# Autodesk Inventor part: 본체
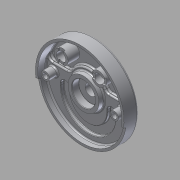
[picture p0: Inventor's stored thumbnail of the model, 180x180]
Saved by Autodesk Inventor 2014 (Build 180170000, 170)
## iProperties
Created: 2015-06
Part Number: 본체
Material: 알루미늄 6061
Document SubType Name: Modeling
Designer: MYHOME
Density: 2.71 g/cm^3
Appearance: 알루미늄 - 평지
Mass: 1069.97 g
Surface Area: 1036.84 cm^2
Volume: 394.821 cm^3
Author: MYHOME
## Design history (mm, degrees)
sketch "스케치1"
  geometry: C1 r 95 at (0, 0); 1 further point
  constraints: 1 centre point, 1 coincident
  dimensions: "d0" = 190 diameter of C1
extrude "돌출1" new body sketch "스케치1" distance "d1" = 32; taper "d2" = 0 deg
sketch "스케치2"
  geometry: C1 r 95 at (0, 0) reference; C2 r 90 at (0, 0)
  constraints: 1 centre point, 1 coincident
  dimensions: "d3" = 180 diameter of C2
extrude "돌출2" cut sketch "스케치2" distance "d4" = 25; taper "d5" = 0 deg
sketch "스케치4"
  geometry: L1 (0, 0)-(-95, 0); L2 (0, 0)-(-94.075, -13.221); L3 (0, 0)-(95, 0); L4 (0, 0)-(94.075, -13.221); A1 r 95 centre (0, 0) between (-95, 0) and (-94.075, -13.221) reference
  constraints: 8 end point, 4 point on circle, 1 collinear, 1 horizontal
  dimensions: "d6" = 8 deg angle of L1 L2; "d7" = 8 deg angle of L4 L3
extrude "돌출3" cut sketch "스케치4" distance "d8" = 5; taper "d9" = 0 deg
sketch "스케치6"
  geometry: L1 (-88.566, 16)-(-38.833, 16); L2 (38.833, 16)-(88.566, 16); A1 r 90 centre (0, 0) between (-88.566, 16) and (88.566, 16) reference; A2 r 42 centre (0, 0) between (38.833, 16) and (-38.833, 16)
  constraints: 4 end point, 4 point on circle, 2 horizontal, 1 centre point, 1 coincident, 1 collinear
  dimensions: "d15" = 42 radius of A2; "d17" = 16 distance from line of A1.centre L2
extrude "돌출4" join sketch "스케치6" distance "d18" = 7; taper "d19" = 0 deg
fillet "모깎기1" dims "d20" = 10
sketch "스케치7"
  geometry: C1 r 15 at (-40, 52); A1 r 90 centre (0, 0) between (85.114, 29.25) and (-85.114, 29.25) reference
  constraints: 1 centre point
  dimensions: "d21" = 30 diameter of C1; "d22" = 40 horizontal distance of A1.centre C1.centre; "d23" = 52 vertical distance of A1.centre C1.centre
extrude "돌출5" join sketch "스케치7" distance "d24" = 25; taper "d25" = 0 deg
sketch "스케치8"
  geometry: C1 r 15 at (0, 0) reference; C2 r 10 at (0, 0); 1 further point
  constraints: 1 centre point, 1 coincident
  dimensions: "d26" = 20 diameter of C2
extrude "돌출6" cut sketch "스케치8" stored distance "d27" = 25; taper "d28" = 0 deg
sketch "스케치9"
  geometry: L1 (-6, 15)-(6, 15); L2 (6, 15)-(6, -15); L3 (6, -15)-(-6, -15); L4 (-6, -15)-(-6, 15); C1 r 10 at (0, 0) reference; C2 r 15 at (0, 0) reference; 2 further points
  constraints: 8 end point, 2 parallel, 2 tangent, 1 horizontal, 1 midpoint, 1 perpendicular, 1 vertical alignment
  dimensions: "d29" = 12 distance of L2.end L3.end
extrude "돌출7" cut sketch "스케치9" distance "d31" = 3; taper "d32" = 0 deg
sketch "스케치10"
  geometry: L1 (-45.033, 16)-(-75.657, 16) reference; L2 (-50, -14)-(-50, -24); L3 (-41, -14)-(-41, -19); L4 (-59, -19)-(-59, -14); L5 (50, -14)-(50, -24); L6 (41, -14)-(41, -19); L7 (59, -19)-(59, -14); A1 r 90 centre (0, 0) between (-85.114, 29.25) and (85.114, 29.25) reference; A2 r 50 centre (0, -19) between (-50, -19) and (50, -19); A3 r 59 centre (0, -19) between (-59, -19) and (59, -19); A4 r 41 centre (0, -19) between (-41, -19) and (41, -19); A5 r 9 centre (-50, -19) between (-41, -19) and (-59, -19); A6 r 9 centre (50, -19) between (59, -19) and (41, -19); A7 r 9 centre (-50, -14) between (-41, -14) and (-59, -14); A8 r 9 centre (50, -14) between (59, -14) and (41, -14); 2 further points
  constraints: 16 end point, 14 point on circle, 8 tangent, 7 centre point, 3 parallel, 2 coincident, 2 horizontal alignment, 2 midpoint, 1 perpendicular, 1 vertical alignment
  dimensions: "d34" = 18 diameter of A6; "d35" = 59 radius of A3; "d36" = 19 distance of A2.centre A1.centre; "d38" = 5 distance of L2.start point (-50, -19); "d41" = 5 distance of L5.start point (50, -19)
extrude "돌출8" cut sketch "스케치10" distance "d42" = 7; taper "d43" = 0 deg
chamfer "모따기1" distance "d44" = 1; stored, may be unused: second distance "d45" = 2, angle "d46" = 45 deg
fillet "모깎기2" dims "d47" = 1
sketch "스케치11"
  geometry: C1 r 35 at (0, 0); A1 r 42 centre (0, 0) between (36.373, 21) and (-36.373, 21) reference
  constraints: 1 centre point, 1 coincident
  dimensions: "d48" = 70 diameter of C1
extrude "돌출9" join sketch "스케치11" distance "d49" = 10; taper "d50" = -10 deg
sketch "스케치12"
  geometry: C1 r 9 at (-74, 0); A1 r 90 centre (0, 0) between (-85.114, 29.25) and (85.114, 29.25) reference
  constraints: 1 centre point, 1 horizontal alignment
  dimensions: "d65" = 18 diameter of C1; "d66" = 74 distance of A1.centre C1.centre
extrude "돌출10" join sketch "스케치12" stored distance "d67" = 10; taper "d68" = 0 deg
fillet "모깎기5" dims "d69" = 3
sketch "스케치13"
  geometry: L1 (-15, 6)-(15, 6); L2 (15, 6)-(15, -6); L3 (15, -6)-(-15, -6); L4 (-15, -6)-(-15, 6); C1 r 10 at (0, 0) reference; C2 r 15 at (0, 0) reference; 2 further points
  constraints: 8 end point, 2 parallel, 2 tangent, 1 horizontal, 1 horizontal alignment, 1 midpoint, 1 perpendicular
  dimensions: "d70" = 12 distance of L1.end L2.end
extrude "돌출11" cut sketch "스케치13" distance "d71" = 3; taper "d72" = 0 deg
sketch "스케치16"
  geometry: C1 r 9 at (74, 0) reference; C2 r 9 at (-74, 0) reference; 2 further points
  constraints: 2 coincident
hole "구멍2" sketch "스케치16" at (74, 0), (-74, 0) diameter "d73" = 11; stored, may be unused: countersink angle "d77" = 90 deg, drill point angle "d79" = 118 deg; dims "d74" = 6, "d75" = 18, "d76" = 11, "d78" = 8
fillet "모깎기6" dims "d80" = 3
fillet "모깎기7" dims "d81" = 3
fillet "모깎기8" dims "d82" = 5
fillet "모깎기9" dims "d83" = 3
sketch "스케치17"
  geometry: C1 r 90 at (0, 0) reference; C2 r 68 at (0, 0)
  constraints: 1 centre point, 1 coincident, 1 other
  dimensions: "d84" = 136 diameter of C2
feature "엠보싱1" sketch "스케치17" dims "d85" = 0.5, "d86" = 0
sketch "스케치18"
  geometry: C1 r 26 at (0, 0)
  constraints: 1 centre point
  dimensions: "d87" = 52 diameter of C1
extrude "돌출12" join sketch "스케치18" distance "d88" = 12; taper "d89" = -15 deg
sketch "스케치19"
  geometry: C1 r 22.785 at (0, 0) reference; C2 r 11.5 at (0, 0)
  constraints: 1 centre point, 1 coincident
  dimensions: "d90" = 23 diameter of C2
extrude "돌출13" cut sketch "스케치19" stored distance "d91" = 12; taper "d92" = 0 deg
fillet "모깎기10" dims "d93" = 3
chamfer "모따기3" distance "d94" = 1; stored, may be unused: second distance "d95" = 2, angle "d96" = 45 deg
fillet "모깎기11" dims "d97" = 3
sketch "스케치20"
  geometry: C1 r 11.5 at (0, 0) reference; C2 r 33.237 at (0, 0) reference; C3 r 25 at (0, 0)
  constraints: 1 centre point, 1 coincident
  dimensions: "d98" = 50 diameter of C3
extrude "돌출14" cut sketch "스케치20" distance "d99" = 15; taper "d100" = 0 deg
chamfer "모따기4" distance "d101" = 1; stored, may be unused: second distance "d102" = 2, angle "d103" = 45 deg
fillet "모깎기12" dims "d104" = 0.3
node "솔리드1"
mirror "대칭1"
mirror "대칭3"
node "투영된 루프1"
node "투영된 루프2"
other parameters: "d16" = 12
